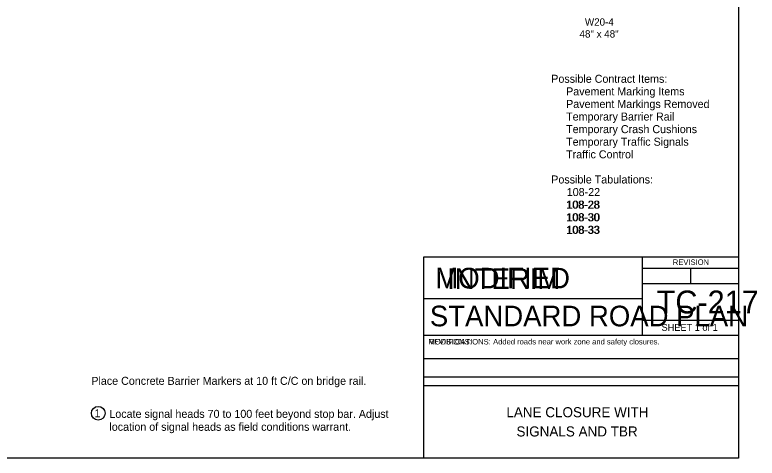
# Model space of a CAD drawing. Extents: x -2134934 to -2119606, y -2139046 to -2137036.
# Drawn here: x -2128679 to -2127057, y -2139046 to -2138077 of the extents above; entities that cross this region are included whole.
import ezdxf

# ---------------------------------------------------------------- set-up
doc = ezdxf.new("R2010")
doc.units = 0
for name, color, linetype in [('Default', 7, 'Continuous'), ('dsnStdBlock', 7, 'Continuous'), ('dsnstdblockInterim', 7, 'Continuous'), ('dsnStdBlockModified', 7, 'Continuous'), ('dsnStdBlockNotModified', 7, 'Continuous'), ('dsnStdLabel', 7, 'Continuous'), ('Level 1', 7, 'Continuous'), ('Level 2', 7, 'Continuous')]:
    doc.layers.add(name, color=color, linetype=linetype)

msp = doc.modelspace()

# ---------------------------------------------------------------- linework, layer by layer
at = {"layer": 'Default'}
msp.add_lwpolyline([(-2130232, -2137035.9), (-2127097, -2137035.9), (-2127097, -2139045.9), (-2130232, -2139045.9)], close=True, dxfattribs=at)
at = {"layer": 'dsnStdBlock'}
for p, q in [((-2127307.9, -2138605.9), (-2127307.9, -2138697.3)), ((-2127307.9, -2138630.9), (-2127097, -2138630.9)), ((-2127202.4, -2138630.9), (-2127202.4, -2138664.1)), ((-2127307.9, -2138664.1), (-2127097, -2138664.1)), ((-2127785, -2138697.3), (-2127307.9, -2138697.3)), ((-2127307.9, -2138697.3), (-2127307.9, -2138777.3)), ((-2127097, -2138745.1), (-2127307.9, -2138745.1)), ((-2127785, -2138777.3), (-2127097, -2138777.3)), ((-2127785, -2138828.3), (-2127097, -2138828.3)), ((-2127785, -2138868.3), (-2127097, -2138868.3)), ((-2127785, -2138887.3), (-2127097, -2138887.3))]:
    msp.add_line(p, q, dxfattribs=at)
msp.add_lwpolyline([(-2127785, -2138605.9), (-2127097, -2138605.9), (-2127097, -2139045.9), (-2127785, -2139045.9)], close=True, dxfattribs=at)
at = {"layer": 'Level 2'}
msp.add_circle((-2128496.7, -2138947.8), 15, dxfattribs=at)

# ---------------------------------------------------------------- texts
at = {"layer": 'dsnStdBlock'}
for s, height, p in [('REVISION', 12, (-2127240.9, -2138623.8)), ('TC-217', 50, (-2127276.2, -2138729.8)), ('STANDARD ROAD PLAN', 45.001, (-2127771.9, -2138757.9)), ('SHEET 1 of 1', 15, (-2127265.5, -2138767.9)), ('Added roads near work zone and safety closures.', 12, (-2127633.7, -2138797.5)), ('LANE CLOSURE WITH', 22, (-2127604.6, -2138956.6)), ('SIGNALS AND TBR', 22, (-2127582.6, -2138998.6))]:
    msp.add_text(s, height=height, dxfattribs=at).set_placement(p)
at = {"layer": 'dsnstdblockInterim'}
msp.add_text('INTERIM', height=45, dxfattribs=at).set_placement((-2127734, -2138676.3))
at = {"layer": 'dsnStdBlockModified'}
for s, height, p in [('MODIFIED', 45, (-2127759.9, -2138675.1)), ('MODIFICATIONS:', 12, (-2127775, -2138797.6))]:
    msp.add_text(s, height=height, dxfattribs=at).set_placement(p)
at = {"layer": 'dsnStdBlockNotModified'}
msp.add_text('REVISIONS:', height=12, dxfattribs=at).set_placement((-2127775, -2138797.6))
at = {"layer": 'dsnStdLabel'}
for s, p in [('W20-4', (-2127433, -2138101.1)), ('48" x 48"', (-2127444.7, -2138127.1))]:
    msp.add_text(s, height=16, dxfattribs=at).set_placement(p)
at = {"layer": 'Level 1'}
for s, p in [('Possible Contract Items:', (-2127506.6, -2138225.9)), ('     Pavement Marking Items', (-2127506.6, -2138253.4)), ('     Pavement Markings Removed', (-2127506.6, -2138280.9)), ('     Temporary Barrier Rail', (-2127506.6, -2138308.4)), ('     Temporary Crash Cushions', (-2127506.6, -2138335.9)), ('     Temporary Traffic Signals', (-2127506.6, -2138363.4)), ('     Traffic Control', (-2127506.6, -2138390.9)), ('Possible Tabulations:', (-2127506.6, -2138445.9)), ('108-22', (-2127472.7, -2138473.3)), ('108-22', (-2127472.7, -2138473.4)), ('     108-28', (-2127506.6, -2138500.9)), ('108-28', (-2127472.7, -2138500.9)), ('     108-30', (-2127506.6, -2138528.4)), ('108-30', (-2127472.7, -2138528.4)), ('     108-33', (-2127506.6, -2138555.9)), ('108-33', (-2127472.7, -2138555.9)), ('Place Concrete Barrier Markers at 10 ft C/C on bridge rail.', (-2128511.7, -2138885.8))]:
    msp.add_text(s, height=17.5, dxfattribs=at).set_placement(p)
at = {"layer": 'Level 2'}
for s, p in [('1', (-2128504.8, -2138956.6)), ('Locate signal heads 70 to 100 feet beyond stop bar. Adjust ', (-2128472.3, -2138957.9)), ('location of signal heads as field conditions warrant.', (-2128472.3, -2138986.2))]:
    msp.add_text(s, height=17.5, dxfattribs=at).set_placement(p)

doc.saveas('drawing.dxf')
